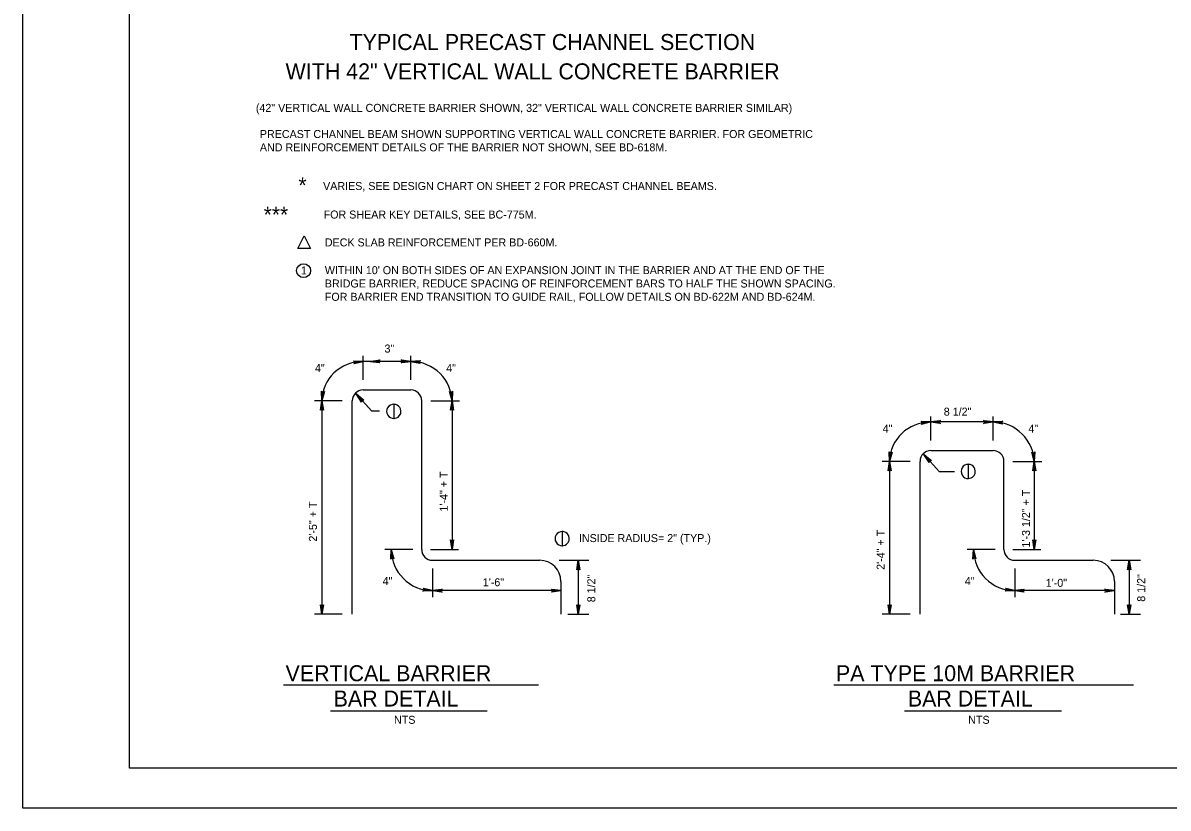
# Model space of a CAD drawing. Extents: x 642009 to 642864, y 298232 to 300014.
# Drawn here: x 642008.7 to 642437.9, y 298231.8 to 298526.3 of the extents above; entities that cross this region are included whole.
import ezdxf

# ---------------------------------------------------------------- set-up
doc = ezdxf.new("R2010")
doc.units = 0
for name, color, linetype in [('1', 7, 'Continuous'), ('2', 7, 'Continuous'), ('22', 7, 'Continuous'), ('PLT-BNDY', 7, 'Continuous')]:
    doc.layers.add(name, color=color, linetype=linetype)

msp = doc.modelspace()

# ---------------------------------------------------------------- linework, layer by layer
at = {"layer": '1'}
for p, q in [((642136.17, 298392.46), (642136.17, 298401.48)), ((642154.07, 298392.46), (642154.07, 298401.48)), ((642154.07, 298399.37), (642136.17, 298399.37)), ((642128.37, 298384.61), (642117.89, 298384.61)), ((642120.72, 298384.61), (642120.72, 298304.53)), ((642133.57, 298387.17), (642139.41, 298380.68)), ((642161.51, 298384.61), (642172.35, 298384.61)), ((642169.52, 298383.92), (642169.52, 298328.83)), ((642142.33, 298380.68), (642139.41, 298380.68)), ((642348.95, 298369.75), (642348.95, 298378.77)), ((642372.28, 298376.65), (642348.95, 298376.65)), ((642372.28, 298369.75), (642372.28, 298378.77)), ((642346.35, 298364.46), (642352.2, 298357.96)), ((642341.16, 298361.89), (642330.67, 298361.89)), ((642333.51, 298361.89), (642333.51, 298304.53)), ((642357.83, 298357.96), (642352.2, 298357.96)), ((642379.68, 298361.89), (642390.57, 298361.89)), ((642387.73, 298361.21), (642387.73, 298328.83)), ((642154.8, 298328.83), (642144.32, 298328.83)), ((642161.45, 298328.83), (642171.93, 298328.83)), ((642373.01, 298328.83), (642362.53, 298328.83)), ((642379.66, 298328.83), (642390.14, 298328.83)), ((642216.79, 298324.78), (642216.79, 298304.53)), ((642423.28, 298324.78), (642423.28, 298304.53)), ((642162.17, 298321.72), (642162.17, 298310.99)), ((642380.38, 298321.72), (642380.38, 298310.99)), ((642210.33, 298313.39), (642162.17, 298313.39)), ((642417.79, 298313.39), (642380.38, 298313.39)), ((642128.37, 298304.53), (642117.89, 298304.53)), ((642341.16, 298304.53), (642330.67, 298304.53))]:
    msp.add_line(p, q, dxfattribs=at)
for points in [[(642111.65, 298441.75), (642114.06, 298446.44), (642116.47, 298441.75)], [(642147.65, 298383.29), (642147.65, 298377.98), (642148.14, 298378.05), (642148.73, 298378.21), (642149.28, 298378.52), (642149.85, 298379.14), (642150.26, 298379.88), (642150.31, 298380.74), (642150.14, 298381.63), (642149.88, 298382.1), (642149.47, 298382.58), (642148.97, 298382.94), (642148.42, 298383.18), (642148.07, 298383.25)], [(642362.95, 298360.77), (642362.95, 298355.45), (642363.44, 298355.52), (642364.04, 298355.69), (642364.59, 298356), (642365.16, 298356.62), (642365.56, 298357.36), (642365.61, 298358.22), (642365.44, 298359.1), (642365.18, 298359.58), (642364.78, 298360.05), (642364.28, 298360.41), (642363.73, 298360.65), (642363.37, 298360.72)], [(642210.77, 298335.57), (642210.77, 298330.25), (642211.26, 298330.32), (642211.86, 298330.49), (642212.4, 298330.8), (642212.98, 298331.42), (642213.38, 298332.16), (642213.43, 298333.02), (642213.26, 298333.9), (642213, 298334.38), (642212.59, 298334.85), (642212.09, 298335.21), (642211.55, 298335.45), (642211.19, 298335.52)]]:
    msp.add_lwpolyline(points, close=True, dxfattribs=at)
for points in [[(642132.73, 298399.46), (642132.89, 298399.23), (642136.17, 298399.37), (642132.73, 298399.46), (642132.55, 298399.59), (642136.17, 298399.37), (642132.92, 298398.88), (642132.83, 298398.63), (642136.17, 298399.37), (642132.66, 298398.45), (642132.83, 298398.63)], [(642142.27, 298398.94), (642142.14, 298399.19), (642138.86, 298399.37), (642142.27, 298398.94), (642142.44, 298398.79), (642138.86, 298399.37), (642142.14, 298399.53), (642142.26, 298399.77), (642138.86, 298399.37), (642142.44, 298399.94), (642142.26, 298399.77)], [(642150.67, 298399.79), (642150.79, 298399.55), (642154.07, 298399.37), (642150.67, 298399.79), (642150.49, 298399.94), (642154.07, 298399.37), (642150.8, 298399.2), (642150.68, 298398.96), (642154.07, 298399.37), (642150.49, 298398.8), (642150.68, 298398.96)], [(642157.44, 298398.71), (642157.33, 298398.97), (642154.07, 298399.37), (642157.44, 298398.71), (642157.61, 298398.55), (642154.07, 298399.37), (642157.35, 298399.31), (642157.49, 298399.54), (642154.07, 298399.37), (642157.68, 298399.69), (642157.49, 298399.54)], [(642121.48, 298387.95), (642121.23, 298387.85), (642120.72, 298384.61), (642121.48, 298387.95), (642121.65, 298388.11), (642120.72, 298384.61), (642120.88, 298387.88), (642120.65, 298388.03), (642120.72, 298384.61), (642120.51, 298388.22), (642120.65, 298388.03)], [(642169.57, 298388.04), (642169.34, 298387.89), (642169.52, 298384.61), (642169.57, 298388.04), (642169.7, 298388.23), (642169.52, 298384.61), (642169, 298387.85), (642168.75, 298387.94), (642169.52, 298384.61), (642168.56, 298388.1), (642168.75, 298387.94)], [(642120.29, 298381.2), (642120.54, 298381.33), (642120.72, 298384.61), (642120.29, 298381.2), (642120.14, 298381.03), (642120.72, 298384.61), (642120.88, 298381.33), (642121.13, 298381.21), (642120.72, 298384.61), (642121.29, 298381.03), (642121.13, 298381.21)], [(642135.53, 298384.36), (642135.62, 298384.61), (642133.57, 298387.17), (642135.53, 298384.36), (642135.53, 298384.13), (642133.57, 298387.17), (642135.88, 298384.85), (642136.14, 298384.92), (642133.57, 298387.17), (642136.38, 298384.89), (642136.14, 298384.92)], [(642169.09, 298381.2), (642169.34, 298381.33), (642169.52, 298384.61), (642169.09, 298381.2), (642168.94, 298381.03), (642169.52, 298384.61), (642169.68, 298381.33), (642169.92, 298381.21), (642169.52, 298384.61), (642170.09, 298381.03), (642169.92, 298381.21)], [(642345.52, 298376.74), (642345.67, 298376.51), (642348.95, 298376.65), (642345.52, 298376.74), (642345.33, 298376.87), (642348.95, 298376.65), (642345.71, 298376.17), (642345.61, 298375.91), (642348.95, 298376.65), (642345.45, 298375.73), (642345.61, 298375.91)], [(642352.36, 298376.22), (642352.23, 298376.47), (642348.95, 298376.65), (642352.36, 298376.22), (642352.53, 298376.07), (642348.95, 298376.65), (642352.23, 298376.81), (642352.35, 298377.06), (642348.95, 298376.65), (642352.53, 298377.22), (642352.35, 298377.06)], [(642368.88, 298377.08), (642369.01, 298376.83), (642372.28, 298376.65), (642368.88, 298377.08), (642368.7, 298377.23), (642372.28, 298376.65), (642369.01, 298376.49), (642368.89, 298376.24), (642372.28, 298376.65), (642368.7, 298376.08), (642368.89, 298376.24)], [(642375.65, 298376), (642375.54, 298376.25), (642372.28, 298376.65), (642375.65, 298376), (642375.82, 298375.83), (642372.28, 298376.65), (642375.56, 298376.59), (642375.7, 298376.83), (642372.28, 298376.65), (642375.89, 298376.98), (642375.7, 298376.83)], [(642334.27, 298365.24), (642334.01, 298365.13), (642333.51, 298361.89), (642334.27, 298365.24), (642334.44, 298365.39), (642333.51, 298361.89), (642333.67, 298365.16), (642333.44, 298365.31), (642333.51, 298361.89), (642333.3, 298365.51), (642333.44, 298365.31)], [(642348.31, 298361.64), (642348.41, 298361.9), (642346.35, 298364.46), (642348.31, 298361.64), (642348.32, 298361.41), (642346.35, 298364.46), (642348.67, 298362.13), (642348.93, 298362.2), (642346.35, 298364.46), (642349.17, 298362.17), (642348.93, 298362.2)], [(642387.79, 298365.32), (642387.55, 298365.17), (642387.73, 298361.89), (642387.79, 298365.32), (642387.91, 298365.51), (642387.73, 298361.89), (642387.21, 298365.13), (642386.96, 298365.22), (642387.73, 298361.89), (642386.78, 298365.39), (642386.96, 298365.22)], [(642333.08, 298358.48), (642333.33, 298358.61), (642333.51, 298361.89), (642333.08, 298358.48), (642332.93, 298358.31), (642333.51, 298361.89), (642333.67, 298358.61), (642333.92, 298358.49), (642333.51, 298361.89), (642334.08, 298358.31), (642333.92, 298358.49)], [(642387.3, 298358.48), (642387.55, 298358.61), (642387.73, 298361.89), (642387.3, 298358.48), (642387.15, 298358.31), (642387.73, 298361.89), (642387.89, 298358.61), (642388.13, 298358.49), (642387.73, 298361.89), (642388.3, 298358.31), (642388.13, 298358.49)], [(642169.94, 298332.24), (642169.7, 298332.11), (642169.52, 298328.83), (642169.94, 298332.24), (642170.09, 298332.41), (642169.52, 298328.83), (642169.35, 298332.11), (642169.11, 298332.23), (642169.52, 298328.83), (642168.95, 298332.41), (642169.11, 298332.23)], [(642388.16, 298332.24), (642387.91, 298332.11), (642387.73, 298328.83), (642388.16, 298332.24), (642388.31, 298332.41), (642387.73, 298328.83), (642387.57, 298332.11), (642387.32, 298332.23), (642387.73, 298328.83), (642387.16, 298332.41), (642387.32, 298332.23)], [(642146.64, 298325.4), (642146.87, 298325.55), (642146.73, 298328.83), (642146.64, 298325.4), (642146.51, 298325.21), (642146.73, 298328.83), (642147.21, 298325.59), (642147.47, 298325.49), (642146.73, 298328.83), (642147.65, 298325.33), (642147.47, 298325.49)], [(642364.85, 298325.4), (642365.09, 298325.55), (642364.94, 298328.83), (642364.85, 298325.4), (642364.72, 298325.21), (642364.94, 298328.83), (642365.43, 298325.59), (642365.68, 298325.49), (642364.94, 298328.83), (642365.86, 298325.33), (642365.68, 298325.49)], [(642216.36, 298321.38), (642216.6, 298321.5), (642216.79, 298324.78), (642216.36, 298321.38), (642216.21, 298321.2), (642216.79, 298324.78), (642216.95, 298321.51), (642217.19, 298321.39), (642216.79, 298324.78), (642217.35, 298321.2), (642217.19, 298321.39)], [(642422.85, 298321.38), (642423.1, 298321.5), (642423.28, 298324.78), (642422.85, 298321.38), (642422.7, 298321.2), (642423.28, 298324.78), (642423.44, 298321.51), (642423.69, 298321.39), (642423.28, 298324.78), (642423.85, 298321.2), (642423.69, 298321.39)], [(642158.84, 298314.21), (642158.94, 298313.95), (642162.17, 298313.39), (642158.84, 298314.21), (642158.68, 298314.38), (642162.17, 298313.39), (642158.9, 298313.61), (642158.75, 298313.38), (642162.17, 298313.39), (642158.55, 298313.24), (642158.75, 298313.38)], [(642165.58, 298312.96), (642165.45, 298313.21), (642162.17, 298313.39), (642165.58, 298312.96), (642165.75, 298312.81), (642162.17, 298313.39), (642165.45, 298313.55), (642165.57, 298313.8), (642162.17, 298313.39), (642165.75, 298313.96), (642165.57, 298313.8)], [(642206.93, 298313.82), (642207.05, 298313.57), (642210.33, 298313.39), (642206.93, 298313.82), (642206.75, 298313.97), (642210.33, 298313.39), (642207.06, 298313.23), (642206.94, 298312.98), (642210.33, 298313.39), (642206.75, 298312.82), (642206.94, 298312.98)], [(642377.05, 298314.21), (642377.15, 298313.95), (642380.38, 298313.39), (642377.05, 298314.21), (642376.9, 298314.38), (642380.38, 298313.39), (642377.11, 298313.61), (642376.96, 298313.38), (642380.38, 298313.39), (642376.76, 298313.24), (642376.96, 298313.38)], [(642383.79, 298312.96), (642383.66, 298313.21), (642380.38, 298313.39), (642383.79, 298312.96), (642383.96, 298312.81), (642380.38, 298313.39), (642383.66, 298313.55), (642383.78, 298313.8), (642380.38, 298313.39), (642383.96, 298313.96), (642383.78, 298313.8)], [(642414.39, 298313.82), (642414.51, 298313.57), (642417.79, 298313.39), (642414.39, 298313.82), (642414.21, 298313.97), (642417.79, 298313.39), (642414.52, 298313.23), (642414.4, 298312.98), (642417.79, 298313.39), (642414.21, 298312.82), (642414.4, 298312.98)], [(642121.15, 298307.93), (642120.9, 298307.81), (642120.72, 298304.53), (642121.15, 298307.93), (642121.3, 298308.11), (642120.72, 298304.53), (642120.56, 298307.8), (642120.32, 298307.92), (642120.72, 298304.53), (642120.15, 298308.11), (642120.32, 298307.92)], [(642217.21, 298307.93), (642216.97, 298307.81), (642216.79, 298304.53), (642217.21, 298307.93), (642217.36, 298308.11), (642216.79, 298304.53), (642216.62, 298307.8), (642216.38, 298307.92), (642216.79, 298304.53), (642216.22, 298308.11), (642216.38, 298307.92)], [(642333.94, 298307.93), (642333.69, 298307.81), (642333.51, 298304.53), (642333.94, 298307.93), (642334.09, 298308.11), (642333.51, 298304.53), (642333.35, 298307.8), (642333.1, 298307.92), (642333.51, 298304.53), (642332.94, 298308.11), (642333.1, 298307.92)], [(642423.71, 298307.93), (642423.46, 298307.81), (642423.28, 298304.53), (642423.71, 298307.93), (642423.86, 298308.11), (642423.28, 298304.53), (642423.12, 298307.8), (642422.87, 298307.92), (642423.28, 298304.53), (642422.71, 298308.11), (642422.87, 298307.92)]]:
    msp.add_lwpolyline(points, dxfattribs=at)
msp.add_circle((642113.87, 298433.42), 2.61, dxfattribs=at)
for centre, radius, start, end in [((642154.07, 298383.92), 15.44, 0, 90), ((642136.17, 298384.61), 4.05, 90, 180), ((642154.07, 298384.61), 4.05, 0, 90), ((642147.65, 298380.64), 2.66, 87.2475, 272.9855), ((642372.28, 298361.21), 15.44, 0, 90), ((642348.95, 298361.89), 4.05, 90, 180), ((642372.28, 298361.89), 4.05, 0, 90), ((642362.95, 298358.11), 2.66, 87.2475, 272.9855), ((642210.77, 298332.91), 2.66, 87.2475, 272.9855), ((642162.17, 298328.83), 15.44, 180, 270), ((642162.17, 298328.83), 4.05, 180, 270), ((642380.38, 298328.83), 15.44, 180, 270), ((642380.38, 298328.83), 4.05, 180, 270)]:
    msp.add_arc(centre, radius, start, end, dxfattribs=at)
for centre in [(642136.17, 298384.61), (642348.95, 298361.89)]:
    msp.add_ellipse(centre, major_axis=(-15.44, 0), ratio=0.95576, start_param=4.712389, end_param=6.283185, dxfattribs=at)
at = {"layer": '2'}
for p, q in [((642048.66, 298246.82), (642048.66, 298810.82)), ((642106.31, 298278.01), (642201.96, 298278.01)), ((642312.64, 298278.01), (642424.86, 298278.01)), ((642123.9, 298268.34), (642182.66, 298268.34)), ((642339.12, 298268.34), (642397.87, 298268.34)), ((642834.66, 298246.82), (642048.66, 298246.82))]:
    msp.add_line(p, q, dxfattribs=at)
at = {"layer": '22'}
for p, q in [((642136.17, 298388.66), (642154.07, 298388.66)), ((642132.12, 298304.53), (642132.12, 298384.61)), ((642158.12, 298328.83), (642158.12, 298384.61)), ((642348.95, 298365.94), (642372.28, 298365.94)), ((642344.9, 298304.53), (642344.9, 298361.89)), ((642376.33, 298328.83), (642376.33, 298361.89)), ((642162.17, 298324.78), (642202.33, 298324.78)), ((642209.67, 298324.78), (642220.75, 298324.78)), ((642380.38, 298324.78), (642409.79, 298324.78)), ((642416.37, 298324.78), (642427.55, 298324.78)), ((642210.33, 298316.78), (642210.33, 298304.53)), ((642417.79, 298316.78), (642417.79, 298304.53)), ((642212.92, 298304.53), (642220.75, 298304.53)), ((642420.03, 298304.53), (642427.55, 298304.53))]:
    msp.add_line(p, q, dxfattribs=at)
for centre in [(642202.33, 298316.78), (642409.79, 298316.78)]:
    msp.add_arc(centre, 8, 0, 90, dxfattribs=at)
at = {"layer": 'PLT-BNDY'}
msp.add_lwpolyline([(642008.66, 298825.82), (642849.66, 298825.82), (642849.66, 298231.82), (642008.66, 298231.82)], close=True, dxfattribs=at)

# ---------------------------------------------------------------- texts
at = {"layer": '2'}
for s, height, p in [('(42" VERTICAL WALL CONCRETE BARRIER SHOWN, 32" VERTICAL WALL CONCRETE BARRIER SIMILAR)', 3, (642095.97, 298492.97)), ('PRECAST CHANNEL BEAM SHOWN SUPPORTING VERTICAL WALL CONCRETE BARRIER. FOR GEOMETRIC ', 3, (642097.47, 298483.16)), ('AND REINFORCEMENT DETAILS OF THE BARRIER NOT SHOWN, SEE BD-618M. ', 3, (642097.47, 298478.16)), ('*', 5.88, (642111.92, 298462.52)), ('VARIES, SEE DESIGN CHART ON SHEET 2 FOR PRECAST CHANNEL BEAMS.', 3, (642121.17, 298463.66)), ('***', 5.88, (642098.9, 298451.5)), ('FOR SHEAR KEY DETAILS, SEE BC-775M.', 2.9997, (642121.37, 298452.96)), ('1', 3, (642112.87, 298432)), ('1\'-6"', 3, (642181.02, 298315.03)), ('1\'-0"', 3, (642392.01, 298314.82)), ('VERTICAL BARRIER', 6, (642107.09, 298279.42)), ('PA TYPE 10M BARRIER', 6, (642313.38, 298279.42)), ('BAR DETAIL', 6, (642125.11, 298269.92)), ('BAR DETAIL', 6, (642340.33, 298269.92))]:
    msp.add_text(s, height=height, dxfattribs=at).set_placement(p)
at = {"layer": '22'}
for s, height, rotation, p in [('TYPICAL PRECAST CHANNEL SECTION', 6, 360, (642131.1, 298516.17)), ('WITH 42" VERTICAL WALL CONCRETE BARRIER', 6, 360, (642107.1, 298505.17)), ('4"', 3, 360, (642118.11, 298395.38)), ('4"', 3, 360, (642330.9, 298372.67)), ('1\'-4" + T', 3, 90, (642167.89, 298343.06)), ('1\'-3 1/2" + T', 2.9997, 90, (642386.1, 298329.56)), ('2\'-5" + T', 3, 90, (642118.85, 298331.79)), ('2\'-4" + T', 3, 90, (642331.63, 298321.2)), ('8 1/2"', 3, 90, (642223.19, 298309.02)), ('8 1/2"', 3, 90, (642429.28, 298309.23))]:
    msp.add_text(s, height=height, rotation=rotation, dxfattribs=at).set_placement(p)
for s, height, p in [('DECK SLAB REINFORCEMENT PER BD-660M.', 2.9997, (642121.82, 298442.51)), ("WITHIN 10' ON BOTH SIDES OF AN EXPANSION JOINT IN THE BARRIER AND AT THE END OF THE ", 2.9997, (642121.82, 298432.1)), ('BRIDGE BARRIER, REDUCE SPACING OF REINFORCEMENT BARS TO HALF THE SHOWN SPACING.', 2.9997, (642121.82, 298427.1)), ('FOR BARRIER END TRANSITION TO GUIDE RAIL, FOLLOW DETAILS ON BD-622M AND BD-624M.', 2.9997, (642121.82, 298422.1)), ('3"', 3, (642144.19, 298402.69)), ('4"', 3, (642167.31, 298395.38)), ('8 1/2"', 3, (642353.79, 298379.03)), ('4"', 3, (642385.52, 298372.67)), ('INSIDE RADIUS= 2" (TYP.)', 2.9997, (642217.05, 298331.6)), ('4"', 3, (642143.47, 298315.51)), ('4"', 3, (642361.68, 298315.51)), ('NTS', 3, (642147.75, 298263.44)), ('NTS', 3, (642362.96, 298263.44))]:
    msp.add_text(s, height=height, dxfattribs=at).set_placement(p)

doc.saveas('drawing.dxf')
